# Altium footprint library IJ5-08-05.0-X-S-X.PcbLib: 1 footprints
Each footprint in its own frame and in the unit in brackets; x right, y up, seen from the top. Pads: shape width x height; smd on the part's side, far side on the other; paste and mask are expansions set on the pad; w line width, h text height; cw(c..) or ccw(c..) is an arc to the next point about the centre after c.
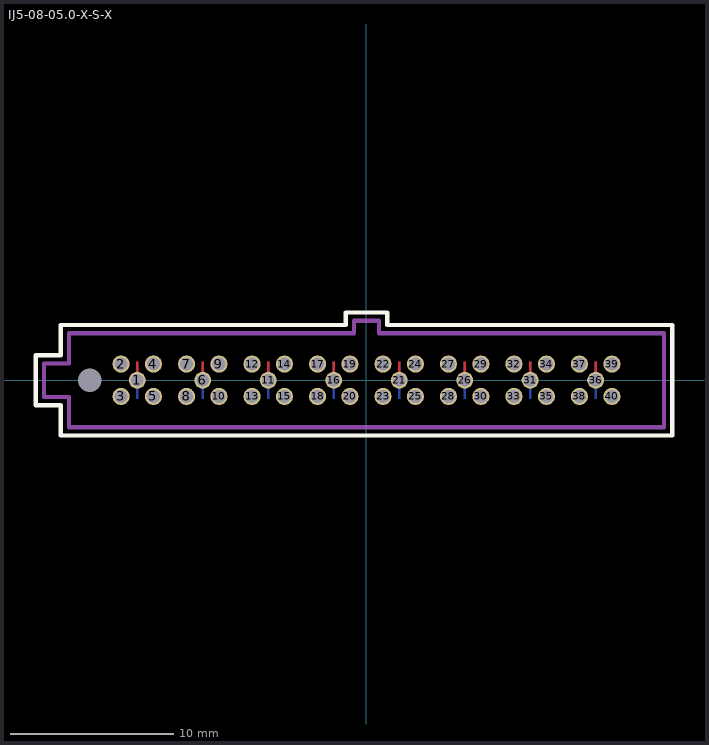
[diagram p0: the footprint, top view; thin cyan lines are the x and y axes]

## IJ5-08-05.0-X-S-X [mil]
pads (41):
  round 41 hole 31 mask+2: 1(-551.25,0) 6(-393.75,0) 11(-236.25,0) 16(-78.75,0) 21(78.75,0) 26(236.25,0) 31(393.75,0) 36(551.25,0)
  round 41 hole 31 mask+3: 2(-590.25,39) 3(-590.25,-39) 4(-512.25,39) 5(-512.25,-39) 7(-432.75,39) 8(-432.75,-39) 9(-354.75,39) 10(-354.75,-39) 12(-275.25,39) 13(-275.25,-39) 14(-197.25,39) 15(-197.25,-39) 17(-117.75,39) 18(-117.75,-39) 19(-39.75,39) 20(-39.75,-39) 22(39.75,39) 23(39.75,-39) 24(117.75,39) 25(117.75,-39) 27(197.25,39) 28(197.25,-39) 29(275.25,39) 30(275.25,-39) 32(354.75,39) 33(354.75,-39) 34(432.75,39) 35(432.75,-39) 37(512.25,39) 38(512.25,-39) 39(590.25,39) 40(590.25,-39)
  round 0 hole 56 unplated: 41(-665.25,0)
Top Layer:
  region: 548.75,44 553.75,44 553.75,0 548.75,0
  region: 391.25,44 396.25,44 396.25,0 391.25,0
  region: 233.75,44 238.75,44 238.75,0 233.75,0
  region: 76.25,44 81.25,44 81.25,0 76.25,0
  region: -81.25,44 -76.25,44 -76.25,0 -81.25,0
  region: -238.75,44 -233.75,44 -233.75,0 -238.75,0
  region: -396.25,44 -391.25,44 -391.25,0 -396.25,0
  region: -553.75,44 -548.75,44 -548.75,0 -553.75,0
Bottom Layer:
  region: 548.75,44 553.75,44 553.75,-44 548.75,-44
  region: 391.25,44 396.25,44 396.25,-44 391.25,-44
  region: 233.75,44 238.75,44 238.75,-44 233.75,-44
  region: 76.25,44 81.25,44 81.25,-44 76.25,-44
  region: -81.25,44 -76.25,44 -76.25,-44 -81.25,-44
  region: -238.75,44 -233.75,44 -233.75,-44 -238.75,-44
  region: -396.25,44 -391.25,44 -391.25,-44 -396.25,-44
  region: -553.75,44 -548.75,44 -548.75,-44 -553.75,-44
Top Overlay:
  lines w10: -795.25,-60 -795.25,60 -735.25,60 -735.25,133 -50,133 -50,163 50,163 50,133 735.25,133 735.25,-133 -735.25,-133 -735.25,-60 -795.25,-60
Top Paste:
  drawing of 40 lines, arcs and shapes, not listed
Bottom Paste:
  drawing of 40 lines, arcs and shapes, not listed
Top Solder:
  region: 546.75,46 555.75,46 555.75,-10 546.75,-10
  region: 389.25,46 398.25,46 398.25,-10 389.25,-10
  region: 231.75,46 240.75,46 240.75,-10 231.75,-10
  region: 74.25,46 83.25,46 83.25,-10 74.25,-10
  region: -83.25,46 -74.25,46 -74.25,-10 -83.25,-10
  region: -240.75,46 -231.75,46 -231.75,-10 -240.75,-10
  region: -398.25,46 -389.25,46 -389.25,-10 -398.25,-10
  region: -555.75,46 -546.75,46 -546.75,-10 -555.75,-10
Bottom Solder:
  region: 546.75,46 555.75,46 555.75,-46 546.75,-46
  region: 389.25,46 398.25,46 398.25,-46 389.25,-46
  region: 231.75,46 240.75,46 240.75,-46 231.75,-46
  region: 74.25,46 83.25,46 83.25,-46 74.25,-46
  region: -83.25,46 -74.25,46 -74.25,-46 -83.25,-46
  region: -240.75,46 -231.75,46 -231.75,-46 -240.75,-46
  region: -398.25,46 -389.25,46 -389.25,-46 -398.25,-46
  region: -555.75,46 -546.75,46 -546.75,-46 -555.75,-46
Mechanical 1:
  lines w10: -775.25,-40 -775.25,40 -715.25,40 -715.25,113 -30,113 -30,143 30,143 30,113 715.25,113 715.25,-113 -715.25,-113 -715.25,-40 -775.25,-40
  text "J1" at -17.57,-18 h30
